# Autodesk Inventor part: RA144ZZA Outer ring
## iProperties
Category: PARTsolutions
Created: 2011-07
Part Number: RA144ZZA Outer ring
Catalog Web Link: www.cadenas.de
Description: Six types or - Inch system sizes
Document SubType Name: Modeling
Designer: PARTsolutions
Density: 1 g/cm^3
NB: RA144ZZA Outer ring
NN: Six types or
NT: Inch system sizes
NBSYN: RA144ZZA Outer ring
LINA: RA144ZZA Outer ring
SD: 3.175
D: 6.350
B: 2.380
B1: 2.779
D1: 7.52
D2: 7.52
C1: 0.58
C2: 0.79
R: 0.08
ORDER: RA144ZZA
CR: 284
COR: 96
CRF: 29
CORF: 10
LSG: 59000
LSO: 70000
MASS: 0.27
ORDER1: R144
WSS: RA144ZA
WDS: RA144ZZA
UTWF: FLR144
FORSS: FLRA144ZA
FORDS: FLRA144ZZA
DA1: 3.9
DA2: 4
DA: 5.5
RAS: 0.08
MASS1: 0.33
VERS: 3
X: 1.587
N: 9
O: 14.954
RB: 0.470
KT: DUMMY
SUPPLIER: NTN
ARTICLENO: RA144ZZA Outer ring
BOMINFO: RA144ZZA Outer ring
CREATOR: CADENAS GmbH
PSOL_IDENT_0: {\\10.0.0.251\ps_data\23d-libs\ntn\ball_roller_bearings\miniature_extra_small_bb\inch_system_sizes\i
PSOL_IDENT_1: ss_or.prj},189 {VTYP=3D},{NB=RA144ZZA Outer ring},{LINA=RA144ZZA Outer ring},{NN=Six types or},{DATE
PSOL_IDENT_2: =11.12.2007 08:48:22},{GEOMDATE=08.02.2007 08:30:00},{VERSION=},{LINEID=16080},{LINESUBID=-1},{WBVAR
PSOL_IDENT_3: =}  {NB=RA144ZZA Outer ring},{LINA=RA144ZZA Outer ring},{KT=DUMMY},{IDNR=},{SD=3.175},{D=6.350},{B=2
PSOL_IDENT_4: .380},{B1=2.779},{D1=7.52},{D2=7.52},{C1=0.58},{C2=0.79},{R=0.08},{ORDER=RA144ZZA},{CR=284},{COR=96}
PSOL_IDENT_5: ,{CRF=29},{CORF=10},{LSG=59000},{LSO=70000},{MASS=0.27},{ORDER1=R144},{WSS=RA144ZA},{WDS=RA144ZZA},{
PSOL_IDENT_6: UTWF=FLR144},{FORSS=FLRA144ZA},{FORDS=FLRA144ZZA},{DA1=3.9},{DA2=4},{DA=5.5},{RAS=0.08},{MASS1=0.33}
PSOL_IDENT_7: ,{VERS=3},{X=1.5875},{N=9},{O=14.95425},{RB=0.4699}
Title: RA144ZZA Outer ring
Author: Cadenas PARTsolutions
Comments: Inch system sizes
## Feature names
1. Revolution1
